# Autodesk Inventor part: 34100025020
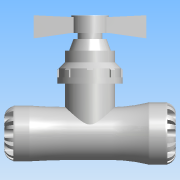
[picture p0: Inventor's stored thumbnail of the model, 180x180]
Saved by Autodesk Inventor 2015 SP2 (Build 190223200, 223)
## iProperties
Created: 2016-12
Part Number: 34100025020
Material: PVC-Piping
Description: Plasson COMPRESSION STOPTAP 25-20 SERIES 1
Document SubType Name: Modeling
Designer: KIM
Mass: 61.7504 g
Surface Area: 140.097 cm^2
Volume: 44.1074 cm^3
Density: 1.4 g/cm^3
Appearance: Smooth - White
Author: KIM
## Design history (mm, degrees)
derived "03410.ipt"
feature "Solid1::03410.ipt"
feature "Solid2::03410.ipt"
tag "TaggingFeature1"
body "Solid1"
other parameters: "d1" = 20.16, "d2" = 25, "d3" = 31.25, "d4" = 47, "d6" = 48, "d8" = 39.95, "d13" = 6.3, "d14" = 6.3, "d15" = 0, "d17" = 360 deg, "d19" = 8 deg, "d20" = 0.5, "d21" = 0.5, "d22" = 8 deg, "d24" = 0, "d26" = 360 deg, "d33" = 4.7, "d35" = 3.125, "d65" = 0.47, "d69" = 129, "d72" = 42, "d73" = 25, "d74" = 18.9, "d75" = 64.5, "d76" = 3.125, "d77" = 48, "d80" = 6.8, "d82" = 6.8, "d83" = 0, "d85" = 360 deg, "d92" = 0, "d94" = 360 deg, "d96" = 89, "d97" = 47, "d98" = 37.6, "d99" = 37.6, "d100" = 135 deg, "d101" = 18.8, "d102" = 70 deg, "d103" = 48.95, "d104" = 71.2, "d105" = 62.3, "d107" = 75.65, "d108" = 84.6, "d110" = 12.015, "d111" = 4.005, "d112" = 14.1, "d113" = 0, "d114" = 49.35, "d115" = 4.7, "d116" = 0, "d117" = 4.7, "d119" = 0, "d121" = 360 deg, "d126" = 0.5, "d127" = 0.5, "d128" = 8 deg, "d129" = 8 deg, "d130" = 0.47, "d132" = 0, "d_" = 25, "E_" = 47, "H_" = 129, "l_" = 48, "A_" = 89, "l_1" = 45, "E_1" = 42, "d9" = 7.875, "d11" = 47, "d12" = 31.25, "d78" = 42, "d79" = 25, "d81" = 8.5, "d109" = 13.35
